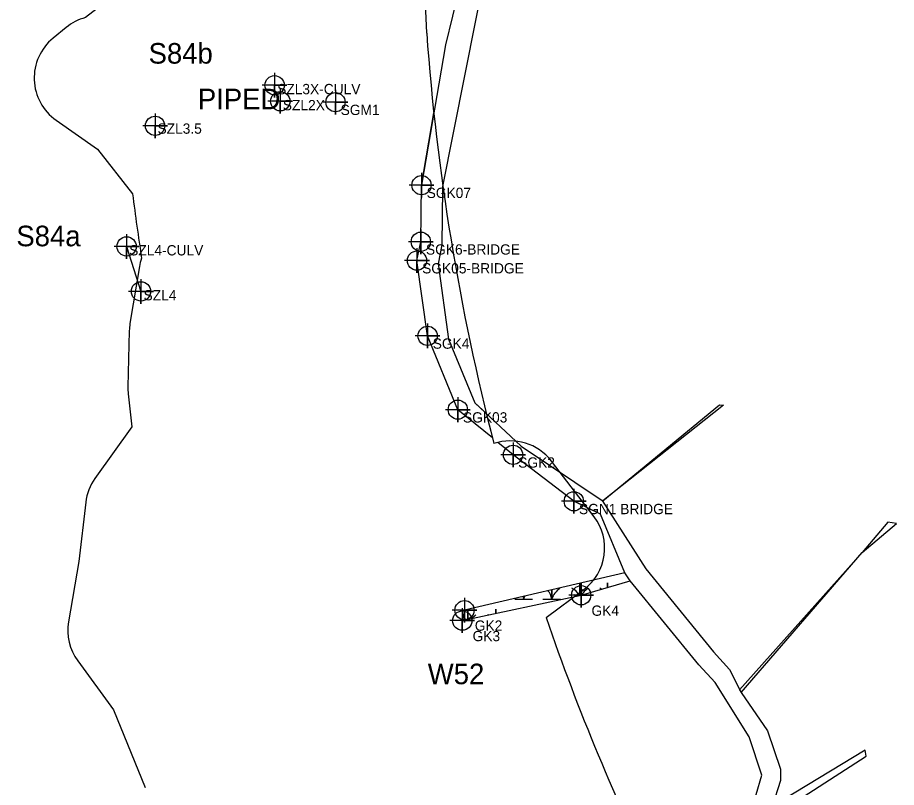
# Model space of a CAD drawing. Extents: x 1253697 to 1278588, y 912189 to 981699.
# Drawn here: x 1254378 to 1255232, y 951321 to 952070 of the extents above; entities that cross this region are included whole.
import ezdxf

# ---------------------------------------------------------------- set-up
doc = ezdxf.new("R2010")
doc.units = 0
for name, color, linetype in [('Default', 7, 'Continuous'), ('Exist Environmental Wetland Boundary', 7, 'Continuous'), ('Exist Environmental Wetland Boundary Cogo Comment', 7, 'Continuous'), ('Exist Environmental Wetland Boundary Cogo Number', 7, 'Continuous'), ('Exist Environmental Wetland Boundary Cogo Point CELL', 7, 'Continuous'), ('Exist Hydro Jurisdictional Stream or Body of Water Mitigable', 7, 'Continuous'), ('Exist Hydro Jurisdictional Stream or Body of Water Mitigable Cogo Comment', 7, 'Continuous'), ('Exist Hydro Jurisdictional Stream or Body of Water Mitigable Cogo Point CELL', 7, 'Continuous'), ('Exist Hydro Jurisdictional Stream or Body of Water NonMitigable', 7, 'Continuous'), ('Exist Hydro Jurisdictional Stream or Body of Water NonMitigable Cogo Comment', 7, 'Continuous'), ('Exist Hydro Jurisdictional Stream or Body of Water NonMitigable Cogo Number', 7, 'Continuous'), ('Exist Hydro Jurisdictional Stream or Body of Water NonMitigable Cogo Point CELL', 7, 'Continuous'), ('Exist Hydro Swamp or Marsh', 7, 'Continuous')]:
    doc.layers.add(name, color=color, linetype=linetype)

msp = doc.modelspace()

# ---------------------------------------------------------------- linework, layer by layer
at = {"layer": 'Default'}
for p, q in [((1254425.08, 952060.13), (1254412.22, 952049.6)), ((1254425.08, 952060.13), (1254412.22, 952049.6)), ((1254425.08, 952060.13), (1254412.22, 952049.6)), ((1254425.08, 952060.13), (1254412.22, 952049.6)), ((1254496.24, 951827.51), (1254487, 951772.05)), ((1254496.24, 951827.51), (1254487, 951772.05)), ((1254496.24, 951827.51), (1254487, 951772.05)), ((1254496.24, 951827.51), (1254487, 951772.05)), ((1254486.33, 951765.05), (1254485, 951710.52)), ((1254486.33, 951765.05), (1254485, 951710.52)), ((1254486.33, 951765.05), (1254485, 951710.52)), ((1254486.33, 951765.05), (1254485, 951710.52)), ((1254938.25, 951584.04), (1254896.68, 951638.35)), ((1254938.25, 951584.04), (1254896.68, 951638.35)), ((1254938.25, 951584.04), (1254896.68, 951638.35)), ((1254938.25, 951584.04), (1254896.68, 951638.35)), ((1254891.56, 951486.18), (1254928.36, 951513.5)), ((1254891.56, 951486.18), (1254928.36, 951513.5)), ((1254891.56, 951486.18), (1254928.36, 951513.5)), ((1254891.56, 951486.18), (1254928.36, 951513.5))]:
    msp.add_line(p, q, dxfattribs=at)
for points in [[(1254775.48, 952054.41), (1254766.9, 952248.99), (1254751.09, 952770.48)], [(1254775.48, 952054.41), (1254766.9, 952248.99), (1254751.09, 952770.48)], [(1254775.48, 952054.41), (1254766.9, 952248.99), (1254751.09, 952770.48)], [(1254775.48, 952054.41), (1254766.9, 952248.99), (1254751.09, 952770.48)], [(1254467.08, 952238.86), (1254473.55, 952092.98), (1254443.69, 952069.7)], [(1254467.08, 952238.86), (1254473.55, 952092.98), (1254443.69, 952069.7)], [(1254467.08, 952238.86), (1254473.55, 952092.98), (1254443.69, 952069.7)], [(1254467.08, 952238.86), (1254473.55, 952092.98), (1254443.69, 952069.7)], [(1254415.23, 951969.95), (1254455.6, 951941.7), (1254489.6, 951898.19)], [(1254415.23, 951969.95), (1254455.6, 951941.7), (1254489.6, 951898.19)], [(1254415.23, 951969.95), (1254455.6, 951941.7), (1254489.6, 951898.19)], [(1254415.23, 951969.95), (1254455.6, 951941.7), (1254489.6, 951898.19)], [(1254485.29, 951703.73), (1254488.88, 951671.66), (1254452.98, 951621.54)], [(1254485.29, 951703.73), (1254488.88, 951671.66), (1254452.98, 951621.54)], [(1254485.29, 951703.73), (1254488.88, 951671.66), (1254452.98, 951621.54)], [(1254485.29, 951703.73), (1254488.88, 951671.66), (1254452.98, 951621.54)], [(1254443.96, 951598.23), (1254437.21, 951540.51), (1254427.19, 951482.1)], [(1254443.96, 951598.23), (1254437.21, 951540.51), (1254427.19, 951482.1)], [(1254443.96, 951598.23), (1254437.21, 951540.51), (1254427.19, 951482.1)], [(1254443.96, 951598.23), (1254437.21, 951540.51), (1254427.19, 951482.1)], [(1254436.19, 951444.02), (1254471.11, 951396.54), (1254501.79, 951320.91)], [(1254436.19, 951444.02), (1254471.11, 951396.54), (1254501.79, 951320.91)], [(1254436.19, 951444.02), (1254471.11, 951396.54), (1254501.79, 951320.91)], [(1254436.19, 951444.02), (1254471.11, 951396.54), (1254501.79, 951320.91)]]:
    msp.add_lwpolyline(points, dxfattribs=at)
for centre, radius, start, end in [((1254456.75, 952021.44), 50, 105.14321, 129.30442), ((1254456.75, 952021.44), 50, 105.14321, 129.30442), ((1254456.75, 952021.44), 50, 105.14321, 129.30442), ((1254456.75, 952021.44), 50, 105.14321, 129.30442), ((1257019.6, 952216.89), 2250, 184.14127, 194.45439), ((1257019.6, 952216.89), 2250, 184.14127, 194.45439), ((1257019.6, 952216.89), 2250, 184.14127, 194.45439), ((1257019.6, 952216.89), 2250, 184.14127, 194.45439), ((1254443.89, 952010.91), 50, 129.30442, 235.02261), ((1254443.89, 952010.91), 50, 129.30442, 235.02261), ((1254443.89, 952010.91), 50, 129.30442, 235.02261), ((1254443.89, 952010.91), 50, 129.30442, 235.02261), ((1257019.6, 952216.89), 2550, 187.17971, 188.60047), ((1257019.6, 952216.89), 2550, 187.17971, 188.60047), ((1257019.6, 952216.89), 2550, 187.17971, 188.60047), ((1257019.6, 952216.89), 2550, 187.17971, 188.60047), ((1254545.56, 951819.29), 50, 161.01516, 170.54129), ((1254545.56, 951819.29), 50, 161.01516, 170.54129), ((1254545.56, 951819.29), 50, 161.01516, 170.54129), ((1254545.56, 951819.29), 50, 161.01516, 170.54129), ((1254536.32, 951763.83), 50, 170.54129, 178.59753), ((1254536.32, 951763.83), 50, 170.54129, 178.59753), ((1254536.32, 951763.83), 50, 170.54129, 178.59753), ((1254536.32, 951763.83), 50, 170.54129, 178.59753), ((1254534.98, 951709.29), 50, 178.59753, 186.38793), ((1254534.98, 951709.29), 50, 178.59753, 186.38793), ((1254534.98, 951709.29), 50, 178.59753, 186.38793), ((1254534.98, 951709.29), 50, 178.59753, 186.38793), ((1254856.98, 951607.95), 50, 37.43436, 108.85025), ((1254856.98, 951607.95), 50, 37.43436, 108.85025), ((1254856.98, 951607.95), 50, 37.43436, 108.85025), ((1254856.98, 951607.95), 50, 37.43436, 108.85025), ((1254493.62, 951592.42), 50, 144.37837, 173.32899), ((1254493.62, 951592.42), 50, 144.37837, 173.32899), ((1254493.62, 951592.42), 50, 144.37837, 173.32899), ((1254493.62, 951592.42), 50, 144.37837, 173.32899), ((1254898.55, 951553.65), 50, 306.59707, 37.43436), ((1254898.55, 951553.65), 50, 306.59707, 37.43436), ((1254898.55, 951553.65), 50, 306.59707, 37.43436), ((1254898.55, 951553.65), 50, 306.59707, 37.43436), ((1254476.47, 951473.64), 50, 170.26774, 216.33354), ((1254476.47, 951473.64), 50, 170.26774, 216.33354), ((1254476.47, 951473.64), 50, 170.26774, 216.33354), ((1254476.47, 951473.64), 50, 170.26774, 216.33354), ((1257019.6, 952216.89), 2250, 198.95116, 206.22316), ((1257019.6, 952216.89), 2250, 198.95116, 206.22316), ((1257019.6, 952216.89), 2250, 198.95116, 206.22316), ((1257019.6, 952216.89), 2250, 198.95116, 206.22316)]:
    msp.add_arc(centre, radius, start, end, dxfattribs=at)
at = {"layer": 'Exist Environmental Wetland Boundary'}
for p, q in [((1254924.21, 951507.53), (1254924.21, 951519.32)), ((1254924.21, 951519.32), (1254924.21, 951507.53)), ((1254815.39, 951484.28), (1254815.39, 951494.04)), ((1254815.39, 951494.04), (1254815.39, 951484.28))]:
    msp.add_line(p, q, dxfattribs=at)
for points in [[(1255060.17, 951693.19), (1255064.02, 951692.84), (1254946.86, 951599.79)], [(1255079.65, 951415.8), (1255081.09, 951413.35), (1255198.83, 951549.38), (1255232.16, 951577.75), (1255223.76, 951579.05), (1255198.83, 951549.38)], [(1254812.24, 951493.3), (1254810.12, 951483.15), (1254925.7, 951507.85), (1254973.3, 951521.96), (1254968, 951529.49)], [(1255111.25, 951302.24), (1255111.27, 951292.2), (1255202.81, 951351.43), (1255201.67, 951357.11)]]:
    msp.add_lwpolyline(points, close=True, dxfattribs=at)
for points in [[(1254951.41, 951515.47), (1254951.41, 951519.93), (1254951.41, 951515.47)], [(1254888.4, 951504.15), (1254897, 951504.15), (1254897, 951513)], [(1254897, 951513), (1254897, 951504.15), (1254905.61, 951504.15)], [(1254861.2, 951504.15), (1254869.8, 951504.15), (1254869.8, 951506.68)], [(1254869.8, 951506.68), (1254869.8, 951504.15), (1254878.4, 951504.15)], [(1254842.6, 951490.09), (1254842.6, 951494.15), (1254842.6, 951490.09)]]:
    msp.add_lwpolyline(points, dxfattribs=at)
for centre, radius, start, end in [((1254884.74, 951503.26), 12.3, 4.14034, 46.1076), ((1254915.25, 951498.09), 19.22, 122.12745, 161.62219), ((1254911.94, 951503.26), 12.3, 19.56861, 67.53497), ((1254942.45, 951498.09), 19.22, 122.12745, 149.26927), ((1254939.14, 951503.26), 12.3, 58.42537, 67.53497), ((1254857.53, 951503.26), 12.3, 4.14034, 15.62941), ((1254888.04, 951498.09), 19.22, 152.55745, 161.62219), ((1254803.13, 951477.48), 12.3, 31.45521, 50.6637), ((1254833.64, 951472.31), 19.22, 122.12745, 138.23511), ((1254830.33, 951477.48), 12.3, 64.64248, 67.53497)]:
    msp.add_arc(centre, radius, start, end, dxfattribs=at)
at = {"layer": 'Exist Environmental Wetland Boundary Cogo Point CELL'}
for points in [[(1254925.7, 951519.85), (1254925.7, 951495.85), (1254925.7, 951507.85), (1254937.7, 951507.85), (1254913.7, 951507.85)], [(1254812.24, 951505.3), (1254812.24, 951481.3), (1254812.24, 951493.3), (1254824.24, 951493.3), (1254800.24, 951493.3)], [(1254810.12, 951495.15), (1254810.12, 951471.15), (1254810.12, 951483.15), (1254822.12, 951483.15), (1254798.12, 951483.15)]]:
    msp.add_lwpolyline(points, dxfattribs=at)
for centre in [(1254925.7, 951507.85), (1254812.24, 951493.3), (1254810.12, 951483.15)]:
    msp.add_circle(centre, 9.38, dxfattribs=at)
at = {"layer": 'Exist Hydro Jurisdictional Stream or Body of Water Mitigable'}
for points in [[(1254790.86, 951903.63), (1254834.69, 952124.1), (1254852.18, 952293.78), (1254854.6, 952377.04), (1254838.85, 952463.96), (1254836.26, 952582.38), (1254849.22, 952615.53), (1254844.93, 952708.35), (1254792.64, 952924.3), (1254783.96, 952943.7), (1254779.03, 952958.29), (1254774.49, 953014.94), (1254774.79, 953039.77), (1254761.12, 953064.04), (1254768.44, 953081.04), (1254748.18, 953170.18), (1254756.4, 953221.52), (1254731.31, 953339.91), (1254770.12, 953501.72), (1254756.74, 953570.93), (1254742.56, 953586.21)], [(1254814.26, 952127.17), (1254793.73, 952043.29), (1254770.44, 951906.7)], [(1254839.39, 951660.86), (1254805.78, 951688.33), (1254776.35, 951760.1), (1254766.06, 951833.34), (1254769.78, 951851.66), (1254770.44, 951906.7), (1254782.43, 951977)], [(1254791.22, 951905.74), (1254790.86, 951903.63), (1254790.21, 951848.6), (1254786.49, 951830.27), (1254796.77, 951757.04), (1254822.33, 951694.88), (1254833.5, 951684.51)], [(1254822.33, 951694.88), (1254867.47, 951652.94), (1254945.99, 951599.86), (1254988.41, 951533.41), (1255054.27, 951452.64), (1255069.77, 951435.76), (1255081.09, 951413.35), (1255106.98, 951376.11), (1255119.32, 951338.83), (1255119.51, 951327.54), (1255111.25, 951302.24), (1255111.27, 951292.2), (1255092.41, 951235.21), (1255080.66, 951105.88), (1255047.6, 951053.53)], [(1254931.35, 951593.06), (1254918.55, 951599.19), (1254859.49, 951644.43), (1254844.79, 951656.45)], [(1255061.79, 951107.6), (1255073.71, 951238.77), (1255101.33, 951332.88), (1255088.99, 951370.15), (1255055.81, 951422.95), (1255039.94, 951440.24), (1254973.3, 951521.96), (1254968, 951529.49), (1254944.31, 951586.85), (1254918.55, 951599.19)]]:
    msp.add_lwpolyline(points, dxfattribs=at)
at = {"layer": 'Exist Hydro Jurisdictional Stream or Body of Water Mitigable Cogo Point CELL'}
for points in [[(1254770.44, 951918.7), (1254770.44, 951894.7), (1254770.44, 951906.7), (1254782.44, 951906.7), (1254758.44, 951906.7)], [(1254769.78, 951863.66), (1254769.78, 951839.66), (1254769.78, 951851.66), (1254781.78, 951851.66), (1254757.78, 951851.66)], [(1254766.06, 951845.34), (1254766.06, 951821.34), (1254766.06, 951833.34), (1254778.06, 951833.34), (1254754.06, 951833.34)], [(1254776.35, 951772.1), (1254776.35, 951748.1), (1254776.35, 951760.1), (1254788.35, 951760.1), (1254764.35, 951760.1)], [(1254805.78, 951700.33), (1254805.78, 951676.33), (1254805.78, 951688.33), (1254817.78, 951688.33), (1254793.78, 951688.33)], [(1254859.49, 951656.43), (1254859.49, 951632.43), (1254859.49, 951644.43), (1254871.49, 951644.43), (1254847.49, 951644.43)], [(1254918.55, 951611.19), (1254918.55, 951587.19), (1254918.55, 951599.19), (1254930.55, 951599.19), (1254906.55, 951599.19)]]:
    msp.add_lwpolyline(points, dxfattribs=at)
for centre in [(1254770.44, 951906.7), (1254769.78, 951851.66), (1254766.06, 951833.34), (1254776.35, 951760.1), (1254805.78, 951688.33), (1254859.49, 951644.43), (1254918.55, 951599.19)]:
    msp.add_circle(centre, 9.38, dxfattribs=at)
at = {"layer": 'Exist Hydro Jurisdictional Stream or Body of Water NonMitigable'}
msp.add_lwpolyline([(1254483.74, 951847.1), (1254497.74, 951803.38)], dxfattribs=at)
at = {"layer": 'Exist Hydro Jurisdictional Stream or Body of Water NonMitigable Cogo Point CELL'}
for points in [[(1254627.6, 952015.9), (1254627.6, 951991.9), (1254627.6, 952003.9), (1254639.6, 952003.9), (1254615.6, 952003.9)], [(1254633.14, 952000.3), (1254633.14, 951976.3), (1254633.14, 951988.3), (1254645.14, 951988.3), (1254621.14, 951988.3)], [(1254686.82, 951999.43), (1254686.82, 951975.43), (1254686.82, 951987.43), (1254698.82, 951987.43), (1254674.82, 951987.43)], [(1254511.45, 951976.44), (1254511.45, 951952.44), (1254511.45, 951964.44), (1254523.45, 951964.44), (1254499.45, 951964.44)], [(1254483.74, 951859.1), (1254483.74, 951835.1), (1254483.74, 951847.1), (1254495.74, 951847.1), (1254471.74, 951847.1)], [(1254497.74, 951815.38), (1254497.74, 951791.38), (1254497.74, 951803.38), (1254509.74, 951803.38), (1254485.74, 951803.38)]]:
    msp.add_lwpolyline(points, dxfattribs=at)
for centre in [(1254627.6, 952003.9), (1254633.14, 951988.3), (1254686.82, 951987.43), (1254511.45, 951964.44), (1254483.74, 951847.1), (1254497.74, 951803.38)]:
    msp.add_circle(centre, 9.38, dxfattribs=at)
at = {"layer": 'Exist Hydro Swamp or Marsh'}
msp.add_lwpolyline([(1254926.45, 951512.08), (1254926.45, 951513.62), (1254926.45, 951512.08)], dxfattribs=at)
msp.add_arc((1254914.18, 951496.95), 12.3, 59.75646, 67.53497, dxfattribs=at)

# ---------------------------------------------------------------- texts
at = {"layer": 'Exist Environmental Wetland Boundary Cogo Comment'}
for s, p in [('GK4', (1254935.7, 951487.85)), ('GK2', (1254822.24, 951473.3)), ('GK3', (1254820.12, 951463.15))]:
    msp.add_text(s, height=10, dxfattribs=at).set_placement(p)
at = {"layer": 'Exist Environmental Wetland Boundary Cogo Number'}
msp.add_text('W52', height=20, dxfattribs=at).set_placement((1254776.52, 951421.29))
at = {"layer": 'Exist Hydro Jurisdictional Stream or Body of Water Mitigable Cogo Comment'}
for s, p in [('SGK07', (1254775.44, 951894.2)), ('SGK6-BRIDGE', (1254774.78, 951839.16)), ('SGK05-BRIDGE', (1254771.06, 951820.84)), ('SGK4', (1254781.35, 951747.6)), ('SGK03', (1254810.78, 951675.83)), ('SGK2', (1254864.49, 951631.93)), ('SGN1 BRIDGE', (1254923.55, 951586.69))]:
    msp.add_text(s, height=10, dxfattribs=at).set_placement(p)
at = {"layer": 'Exist Hydro Jurisdictional Stream or Body of Water NonMitigable Cogo Comment'}
for s, p in [('SZL3X-CULV', (1254630.1, 951995.15)), ('SZL2X', (1254635.64, 951979.55)), ('SGM1', (1254691.82, 951974.93)), ('SZL3.5', (1254513.78, 951956.7))]:
    msp.add_text(s, height=10, dxfattribs=at).set_placement(p)
at = {"layer": 'Exist Hydro Jurisdictional Stream or Body of Water NonMitigable Cogo Number'}
for s, p in [('S84b', (1254505.11, 952024.91)), ('PIPED', (1254553.03, 951980.51)), ('S84a', (1254376.54, 951847.26))]:
    msp.add_text(s, height=20, dxfattribs=at).set_placement(p)
at = {"layer": 'Exist Hydro Jurisdictional Stream or Body of Water NonMitigable Cogo Point CELL'}
for s, p in [('SZL4-CULV', (1254486.24, 951838.35)), ('SZL4', (1254500.24, 951794.63))]:
    msp.add_text(s, height=10, dxfattribs=at).set_placement(p)

doc.saveas('drawing.dxf')
